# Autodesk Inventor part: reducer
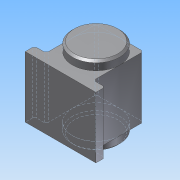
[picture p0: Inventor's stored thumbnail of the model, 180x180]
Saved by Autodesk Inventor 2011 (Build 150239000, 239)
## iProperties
Created: 2020-12
Part Number: reducer
Document SubType Name: Modeling
Designer: PC
Density: 1 g/cm^3
Author: PC
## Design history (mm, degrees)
sketch "Sketch1"
  geometry: L1 (-89.495, -90)-(89.495, -90); L2 (89.495, -90)-(89.495, -66.713); L3 (89.495, -66.713)-(-89.495, -66.713); L4 (-89.495, -66.713)-(-89.495, -90); L5 (0, 87.332)-(0, -130.014); L6 (-60, 0)-(-60, -66.713); L7 (60, 0)-(60, -66.713); L8 (60, 0)-(60, 60); L9 (-60, 0)-(-60, 60); L10 (60, 60)-(-60, 60); A1 r 60 centre (0, 0) between (-60, 0) and (60, 0); 2 further points
  constraints: 20 end point, 5 tangent, 4 parallel, 4 perpendicular, 4 point on line, 2 point on circle, 1 centre point, 1 coincident, 1 collinear, 1 horizontal, 1 midpoint
  dimensions: "d0" = 120 diameter of A1; "d1" = 90 distance from line of point (0, 0) L1
extrude "Extrusion1" new body sketch "Sketch1" stored distance "d2" = 155; taper "d3" = 0 deg
extrude "Extrusion2" join sketch "Sketch1" stored distance "d4" = 200; taper "d5" = 0 deg
chamfer "Chamfer1" distance "d6" = 5; stored, may be unused: second distance "d7" = 2, angle "d8" = 45 deg
body "Solid1"
